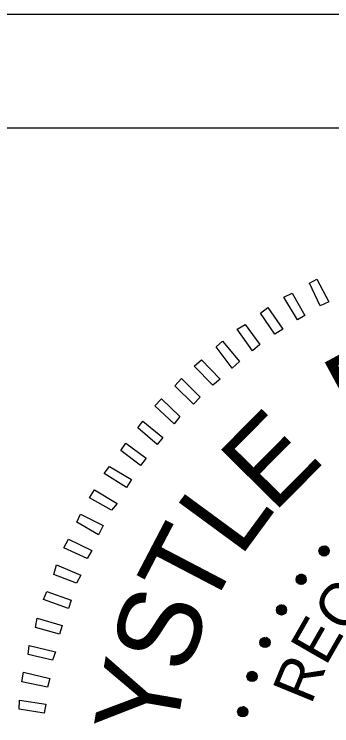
# Model space of a CAD drawing. Extents: x 1577619 to 1828281, y 483481 to 598136.
# Drawn here: x 1707854 to 1708972, y 513680 to 516185 of the extents above; entities that cross this region are included whole.
import ezdxf

# ---------------------------------------------------------------- set-up
doc = ezdxf.new("R2010")
doc.units = 0
doc.layers.add('DESIGN - SHEET - Linework', color=7, linetype='Continuous')
doc.layers.add('Volkert Engineer Seal', color=7, linetype='Continuous')

msp = doc.modelspace()

# ---------------------------------------------------------------- linework, layer by layer
at = {"layer": 'DESIGN - SHEET - Linework'}
msp.add_line((1706804.8, 515784.6), (1712904.8, 515784.6), dxfattribs=at)
msp.add_lwpolyline([(1712904.8, 511184.6), (1706804.8, 511184.6), (1706804.8, 516184.6), (1712904.8, 516184.6)], close=True, dxfattribs=at)
at = {"layer": 'Volkert Engineer Seal'}
for p, q in [((1708948.4, 514277.6), (1708926.6, 514297.2)), ((1708945.1, 514277.1), (1708926.6, 514293.8)), ((1708951.2, 514278.4), (1708927.2, 514300.1)), ((1708953.7, 514279.7), (1708928.2, 514302.6)), ((1708955.8, 514281.2), (1708929.5, 514304.9)), ((1708957.7, 514282.9), (1708931, 514306.9)), ((1708959.3, 514284.9), (1708932.8, 514308.7)), ((1708960.6, 514287.1), (1708934.9, 514310.2)), ((1708961.6, 514289.6), (1708937.3, 514311.5)), ((1708962.2, 514292.5), (1708940, 514312.4)), ((1708962.4, 514295.7), (1708943.3, 514313)), ((1708961.8, 514299.7), (1708947.3, 514312.8)), ((1708958.9, 514305.7), (1708953.6, 514310.5)), ((1708940.9, 514277.5), (1708927.3, 514289.7)), ((1708869.8, 514178.1), (1708846.1, 514195.4)), ((1708872.5, 514179.3), (1708846.4, 514198.3)), ((1708874.8, 514180.8), (1708847.1, 514200.9)), ((1708876.8, 514182.5), (1708848.1, 514203.3)), ((1708878.4, 514184.4), (1708849.4, 514205.5)), ((1708879.8, 514186.6), (1708851, 514207.5)), ((1708880.9, 514188.9), (1708853, 514209.2)), ((1708881.6, 514191.5), (1708855.2, 514210.7)), ((1708882, 514194.4), (1708857.8, 514212)), ((1708881.8, 514197.7), (1708861, 514212.8)), ((1708880.8, 514201.6), (1708865, 514213)), ((1708877.3, 514207.3), (1708871.5, 514211.4)), ((1708866.6, 514177.4), (1708846.4, 514192)), ((1708862.4, 514177.3), (1708847.6, 514188)), ((1708808.5, 514076.1), (1708777.8, 514093.9)), ((1708809.9, 514078.2), (1708778.9, 514096.2)), ((1708811.1, 514080.5), (1708780.3, 514098.3)), ((1708811.9, 514083), (1708782, 514100.2)), ((1708812.4, 514085.6), (1708784.1, 514102)), ((1708812.4, 514088.5), (1708786.6, 514103.4)), ((1708811.9, 514091.8), (1708789.6, 514104.6)), ((1708810.5, 514095.5), (1708793.6, 514105.3)), ((1708806.4, 514100.8), (1708800.2, 514104.4)), ((1708804.6, 514072.5), (1708776.6, 514088.7)), ((1708802, 514071.1), (1708776.6, 514085.7)), ((1708806.7, 514074.2), (1708777, 514091.4)), ((1708798.9, 514070), (1708777.3, 514082.4)), ((1708794.7, 514069.4), (1708778.9, 514078.6)), ((1708748.2, 513959.2), (1708718.7, 513972.3)), ((1708750.1, 513961.1), (1708718.8, 513975.1)), ((1708745.8, 513957.5), (1708719, 513969.4)), ((1708751.7, 513963.2), (1708719.3, 513977.6)), ((1708752.9, 513965.4), (1708720.2, 513980)), ((1708753.8, 513967.8), (1708721.3, 513982.3)), ((1708754.4, 513970.3), (1708722.8, 513984.4)), ((1708754.6, 513973), (1708724.7, 513986.3)), ((1708754.3, 513975.9), (1708727, 513988.1)), ((1708753.5, 513979.1), (1708730, 513989.6)), ((1708751.7, 513982.7), (1708733.8, 513990.6)), ((1708747, 513987.5), (1708740.5, 513990.4)), ((1708742.8, 513956.1), (1708720, 513966.2)), ((1708738.7, 513955.1), (1708722, 513962.5)), ((1708707.1, 513860.9), (1708682.6, 513868.9)), ((1708705, 513864.3), (1708686.4, 513870.4)), ((1708699.8, 513868.7), (1708693.1, 513870.8)), ((1708705.7, 513842.7), (1708673.1, 513853.3)), ((1708704, 513840.6), (1708673.2, 513850.6)), ((1708707, 513844.9), (1708673.3, 513855.9)), ((1708708, 513847.3), (1708673.9, 513858.4)), ((1708701.8, 513838.7), (1708673.9, 513847.7)), ((1708708.7, 513849.8), (1708674.8, 513860.8)), ((1708698.9, 513836.9), (1708675.2, 513844.6)), ((1708708.9, 513852.3), (1708676.1, 513863)), ((1708708.8, 513855), (1708677.8, 513865.1)), ((1708708.3, 513857.9), (1708679.9, 513867.1)), ((1708695, 513835.5), (1708677.5, 513841.2)), ((1708673.4, 513738.6), (1708648.2, 513743.9)), ((1708670.9, 513741.7), (1708651.8, 513745.8)), ((1708665.3, 513745.5), (1708658.4, 513747)), ((1708675, 513722.7), (1708640.3, 513730.1)), ((1708673.9, 513720.3), (1708640.3, 513727.4)), ((1708675.7, 513725.1), (1708640.6, 513732.6)), ((1708672.4, 513718), (1708640.8, 513724.8)), ((1708676.1, 513727.6), (1708641.3, 513735)), ((1708670.4, 513715.9), (1708641.7, 513722)), ((1708676.1, 513730.2), (1708642.3, 513737.4)), ((1708667.7, 513713.8), (1708643.3, 513719)), ((1708675.7, 513732.9), (1708643.8, 513739.7)), ((1708674.9, 513735.7), (1708645.7, 513741.9)), ((1708663.9, 513712), (1708646, 513715.9))]:
    msp.add_line(p, q, dxfattribs=at)
for points in [[(1708930.8, 515158.2), (1708892.8, 515238.2), (1708918.8, 515252.2), (1708960.8, 515172.2)], [(1708850.8, 515108.2), (1708802.8, 515188.2), (1708832.8, 515202.2), (1708876.8, 515124.2)], [(1708770.8, 515058.2), (1708720.8, 515132.2), (1708746.8, 515152.2), (1708798.8, 515076.2)], [(1708692.8, 515000.2), (1708638.8, 515076.2), (1708666.8, 515092.2), (1708718.8, 515022.2)], [(1708620.8, 514938.2), (1708564.8, 515014.2), (1708586.8, 515034.2), (1708646.8, 514962.2)], [(1708552.8, 514878.2), (1708486.8, 514946.2), (1708512.8, 514968.2), (1708578.8, 514900.2)], [(1708484.8, 514812.2), (1708418.8, 514876.2), (1708442.8, 514902.2), (1708508.8, 514836.2)], [(1708416.8, 514742.2), (1708348.8, 514806.2), (1708372.8, 514830.2), (1708436.8, 514768.2)], [(1708356.8, 514670.2), (1708288.8, 514728.2), (1708306.8, 514752.2), (1708376.8, 514694.2)], [(1708298.8, 514596.2), (1708228.8, 514648.2), (1708246.8, 514674.2), (1708318.8, 514622.2)], [(1708248.8, 514518.2), (1708170.8, 514568.2), (1708188.8, 514592.2), (1708266.8, 514546.2)], [(1708196.8, 514438.2), (1708118.8, 514482.2), (1708136.8, 514510.2), (1708216.8, 514462.2)], [(1708150.8, 514352.2), (1708074.8, 514396.2), (1708086.8, 514424.2), (1708166.8, 514384.2)], [(1708110.8, 514268.2), (1708028.8, 514306.2), (1708044.8, 514336.2), (1708126.8, 514296.2)], [(1708072.8, 514182.2), (1707992.8, 514212.2), (1708002.8, 514246.2), (1708088.8, 514210.2)], [(1708044.8, 514092.2), (1707956.8, 514124.2), (1707968.8, 514152.2), (1708054.8, 514122.2)], [(1708012.8, 514002.2), (1707928.8, 514026.2), (1707934.8, 514058.2), (1708022.8, 514032.2)], [(1707988.8, 513910.2), (1707902.8, 513930.2), (1707906.8, 513962.2), (1707998.8, 513940.2)], [(1707970.8, 513816.2), (1707880.8, 513834.2), (1707886.8, 513868.2), (1707978.8, 513846.2)], [(1707958.8, 513724.2), (1707870.8, 513738.2), (1707872.8, 513770.2), (1707964.8, 513756.2)]]:
    msp.add_lwpolyline(points, close=True, dxfattribs=at)
for centre in [(1708944.5, 514295), (1708864, 514195.1), (1708794.5, 514087.4), (1708736.6, 513972.9), (1708691, 513853), (1708658.2, 513729)]:
    msp.add_circle(centre, 17.9, dxfattribs=at)

# ---------------------------------------------------------------- texts
for s, height, rotation, p in [('D', 290, 28.4009, (1709057, 514688.6)), ('E', 290, 45.3582, (1708766, 514425)), ('L', 290, 53.6997, (1708648.3, 514268.4)), ('T', 290, 62.4055, (1708537.8, 514067.8)), ('G', 150, 52.7658, (1709017.4, 513999.6)), ('S', 290, 71.3299, (1708461.2, 513853.4)), ('E', 150, 60.2097, (1708950.3, 513887.2)), ('Y', 290, 80.1452, (1708419, 513629.2)), ('R', 150, 67.6533, (1708898.5, 513751.1))]:
    msp.add_text(s, height=height, rotation=rotation, dxfattribs=at).set_placement(p)

doc.saveas('drawing.dxf')
